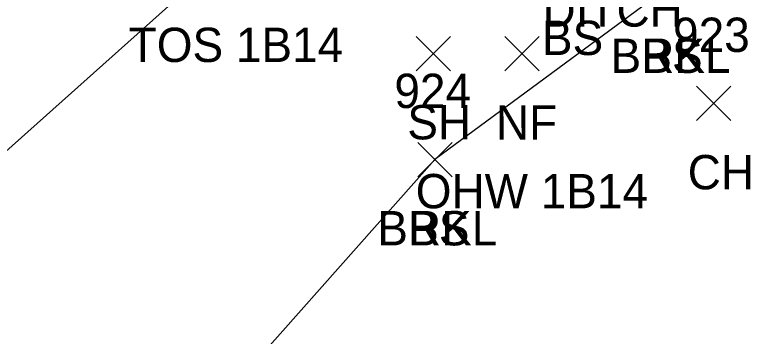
# Model space of a CAD drawing. Extents: x 1528286 to 1556263, y 492387 to 508952.
# Drawn here: x 1528472.83 to 1528516.34, y 492589.21 to 492607.91 of the extents above; entities that cross this region are included whole.
import ezdxf

# ---------------------------------------------------------------- set-up
doc = ezdxf.new("R2010")
doc.units = 0
for name, color, linetype in [('D_A', 7, 'Continuous'), ('L_A', 7, 'Continuous'), ('L_C', 7, 'Continuous'), ('L_I', 7, 'Continuous'), ('L_TIC', 7, 'Continuous'), ('LAWA', 7, 'Continuous'), ('LAWE', 7, 'Continuous'), ('LELB', 7, 'Continuous')]:
    doc.layers.add(name, color=color, linetype=linetype)

msp = doc.modelspace()

# ---------------------------------------------------------------- linework, layer by layer
at = {"layer": 'L_TIC'}
for points in [[(1528496.195, 492604.663), (1528498.195, 492606.663)], [(1528498.195, 492604.663), (1528496.195, 492606.663)], [(1528496.195, 492604.663), (1528498.195, 492606.663)], [(1528498.195, 492604.663), (1528496.195, 492606.663)], [(1528501.362, 492604.648), (1528503.362, 492606.648)], [(1528503.362, 492604.648), (1528501.362, 492606.648)], [(1528501.362, 492604.648), (1528503.362, 492606.648)], [(1528503.362, 492604.648), (1528501.362, 492606.648)], [(1528512.521, 492601.754), (1528514.521, 492603.754)], [(1528514.521, 492601.754), (1528512.521, 492603.754)], [(1528512.521, 492601.754), (1528514.521, 492603.754)], [(1528514.521, 492601.754), (1528512.521, 492603.754)], [(1528496.291, 492598.489), (1528498.291, 492600.489)], [(1528498.291, 492598.489), (1528496.291, 492600.489)], [(1528496.291, 492598.489), (1528498.291, 492600.489)], [(1528498.291, 492598.489), (1528496.291, 492600.489)], [(1528496.291, 492598.489), (1528498.291, 492600.489)], [(1528498.291, 492598.489), (1528496.291, 492600.489)], [(1528496.291, 492598.489), (1528498.291, 492600.489)], [(1528498.291, 492598.489), (1528496.291, 492600.489)]]:
    msp.add_lwpolyline(points, dxfattribs=at)
at = {"layer": 'LAWA'}
msp.add_lwpolyline([(1528350.567, 492486.658), (1528374.131, 492513.994), (1528413.925, 492550.925), (1528435.091, 492569.848), (1528453.537, 492583.197), (1528487.048, 492613.162), (1528503.178, 492626.813), (1528522.579, 492648.478), (1528559.072, 492677.555), (1528579.271, 492695.125), (1528598.445, 492712.961), (1528609.007, 492715.026)], dxfattribs=at)
msp.add_lwpolyline([(1528350.567, 492486.658), (1528374.131, 492513.994), (1528413.925, 492550.925), (1528435.091, 492569.848), (1528453.537, 492583.197), (1528487.048, 492613.162), (1528503.178, 492626.813), (1528522.579, 492648.478), (1528559.072, 492677.555), (1528579.271, 492695.125), (1528598.445, 492712.961), (1528609.007, 492715.026)], dxfattribs=at)
at = {"layer": 'LAWE'}
msp.add_lwpolyline([(1528639.893, 492735.148), (1528628.638, 492716.197), (1528619.322, 492697.772), (1528600.014, 492685.78), (1528586.494, 492675.208), (1528555.765, 492651.711), (1528552.059, 492644.142), (1528537.626, 492632.534), (1528523.345, 492621.851), (1528510.87, 492609.533), (1528497.291, 492599.489), (1528482.777, 492583.151), (1528460.774, 492562.048), (1528436.992, 492551.704), (1528418.951, 492545.204), (1528399.482, 492529.93), (1528387.952, 492519.312), (1528358.196, 492480.955)], dxfattribs=at)
msp.add_lwpolyline([(1528639.893, 492735.148), (1528628.638, 492716.197), (1528619.322, 492697.772), (1528600.014, 492685.78), (1528586.494, 492675.208), (1528555.765, 492651.711), (1528552.059, 492644.142), (1528537.626, 492632.534), (1528523.345, 492621.851), (1528510.87, 492609.533), (1528497.291, 492599.489), (1528482.777, 492583.151), (1528460.774, 492562.048), (1528436.992, 492551.704), (1528418.951, 492545.204), (1528399.482, 492529.93), (1528387.952, 492519.312), (1528358.196, 492480.955)], dxfattribs=at)
at = {"layer": 'LELB'}
for points in [[(1528619.629, 492709.303), (1528607.886, 492695.261), (1528600.014, 492685.78), (1528586.494, 492675.208), (1528555.765, 492651.711), (1528552.059, 492644.142), (1528537.626, 492632.534), (1528523.345, 492621.851), (1528510.87, 492609.533), (1528497.291, 492599.489), (1528482.777, 492583.151), (1528460.774, 492562.048), (1528436.992, 492551.704), (1528418.951, 492545.204), (1528399.482, 492529.93), (1528387.952, 492519.312), (1528358.196, 492480.955)], [(1528619.629, 492709.303), (1528607.886, 492695.261), (1528600.014, 492685.78), (1528586.494, 492675.208), (1528555.765, 492651.711), (1528552.059, 492644.142), (1528537.626, 492632.534), (1528523.345, 492621.851), (1528510.87, 492609.533), (1528497.291, 492599.489), (1528482.777, 492583.151), (1528460.774, 492562.048), (1528436.992, 492551.704), (1528418.951, 492545.204), (1528399.482, 492529.93), (1528387.952, 492519.312), (1528358.196, 492480.955)], [(1528407.988, 492556.109), (1528435.091, 492569.848), (1528453.537, 492583.197), (1528487.048, 492613.162), (1528483.53, 492620.801)], [(1528407.988, 492556.109), (1528435.091, 492569.848), (1528453.537, 492583.197), (1528487.048, 492613.162), (1528483.53, 492620.801)]]:
    msp.add_lwpolyline(points, dxfattribs=at)

# ---------------------------------------------------------------- texts
at = {"layer": 'D_A'}
msp.add_text('DITCH', height=2, dxfattribs=at).set_placement((1528503.554, 492607.229))
msp.add_text('DITCH', height=2, dxfattribs=at).set_placement((1528503.554, 492607.229))
at = {"layer": 'L_A'}
for s, p in [('BS', (1528503.519, 492605.576)), ('BS', (1528503.519, 492605.576)), ('BRKL', (1528507.516, 492604.533)), ('BRKL', (1528507.516, 492604.533)), ('BS', (1528509.311, 492604.533)), ('BS', (1528509.311, 492604.533)), ('SH', (1528495.683, 492600.663)), ('SH', (1528495.683, 492600.663)), ('NF', (1528500.842, 492600.648)), ('NF', (1528500.842, 492600.648)), ('CH', (1528512.009, 492597.754)), ('CH', (1528512.009, 492597.754)), ('BRKL', (1528493.936, 492594.489)), ('BRKL', (1528493.936, 492594.489)), ('BS', (1528495.732, 492594.489)), ('BS', (1528495.732, 492594.489))]:
    msp.add_text(s, height=2, dxfattribs=at).set_placement(p)
at = {"layer": 'L_C'}
for s, p in [('TOS 1B14', (1528479.46, 492605.169)), ('TOS 1B14', (1528479.46, 492605.169)), ('OHW 1B14', (1528496.173, 492596.648)), ('OHW 1B14', (1528496.173, 492596.648))]:
    msp.add_text(s, height=2, dxfattribs=at).set_placement(p)
at = {"layer": 'L_I'}
for s, p in [('923', (1528511.159, 492605.754)), ('923', (1528511.159, 492605.754)), ('924', (1528494.928, 492602.489)), ('924', (1528494.928, 492602.489)), ('924', (1528494.928, 492602.489)), ('924', (1528494.928, 492602.489))]:
    msp.add_text(s, height=2, dxfattribs=at).set_placement(p)

doc.saveas('drawing.dxf')
